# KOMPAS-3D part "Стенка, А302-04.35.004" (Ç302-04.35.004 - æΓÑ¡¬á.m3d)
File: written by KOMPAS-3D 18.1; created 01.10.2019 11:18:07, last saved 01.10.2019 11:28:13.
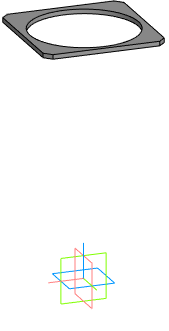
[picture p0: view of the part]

Document properties: Полное имя файла: D:\Мембранные насосы\Мембранный электропривод\А302-00.00.000 - ASTRA-302 (МЭ200)\3Д ПВХ\А302-04.35.004 - Стенка.m3d

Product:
- Part/product: Стенка  | designation А302-04.35.004
    Масса: 0.256038

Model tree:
1. Эскиз:2  (with: Операция выдавливания:1, Элемент выдавливания:2)  (labels: Труба 140х140х6; А302-01.35.000 - Фланец.a3d)
2. Элемент выдавливания:1
     Расстояние 1 = 5
3. Эскиз:4  (with: Элемент выдавливания:1)
4. Элемент выдавливания:2
     Расстояние 2 = 10

Referenced files in D:\Мембранные насосы\Мембранный электропривод\А302-00.00.000 - ASTRA-302 (МЭ200)\3Д ПВХ\: А302-01.35.000 - Фланец.a3d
